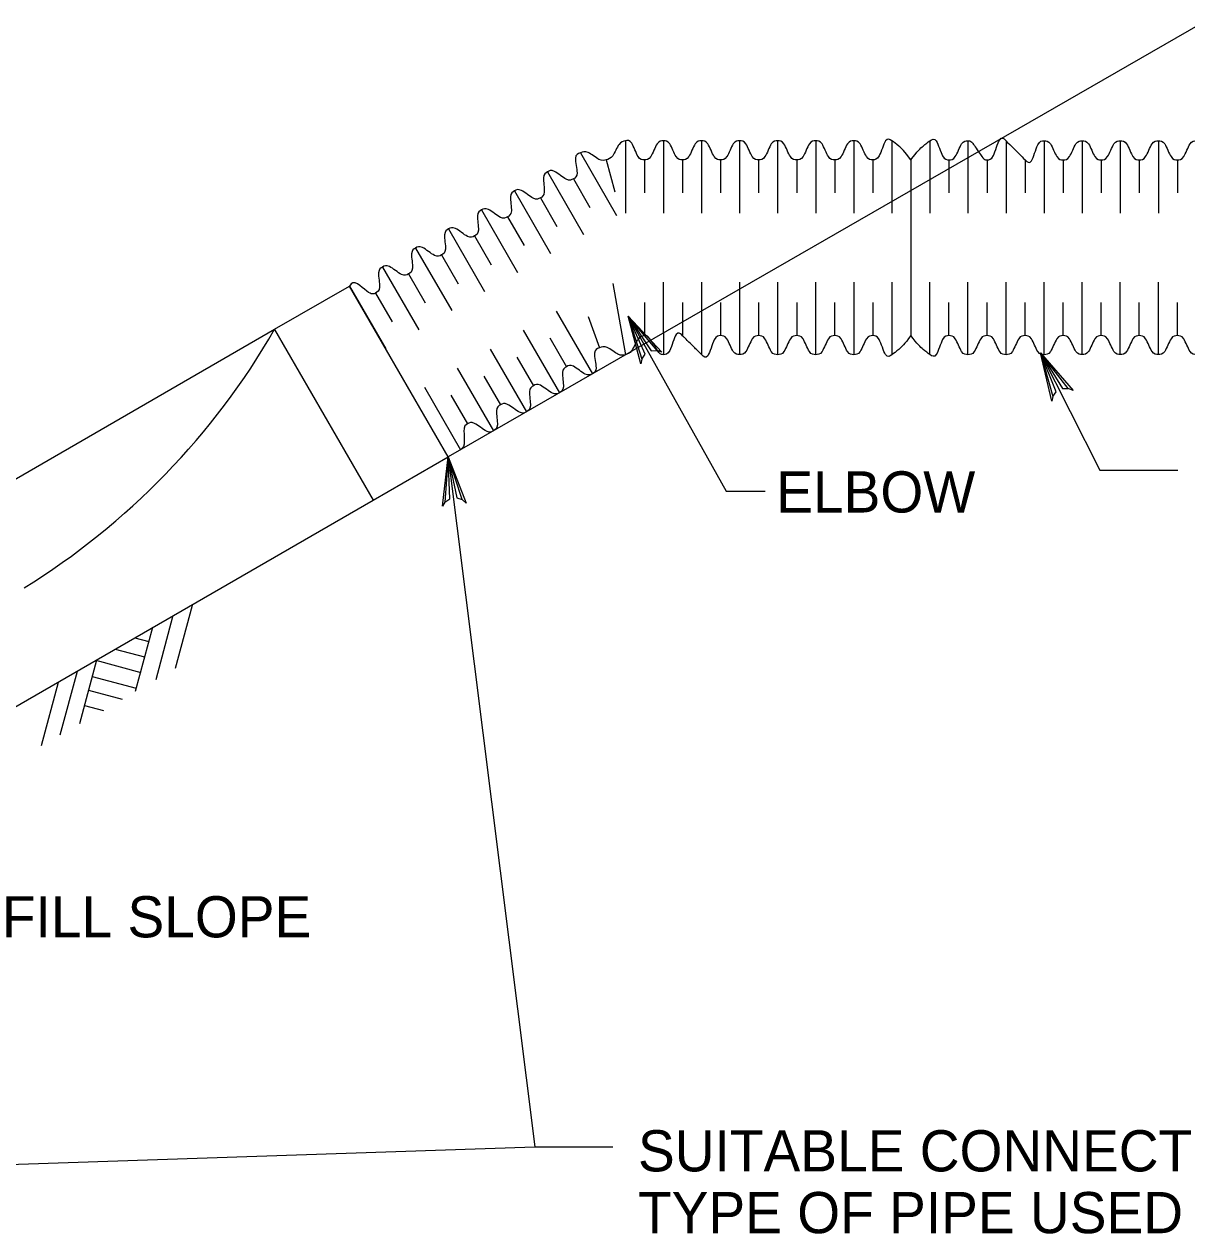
# Model space of a CAD drawing. Extents: x 636462 to 637367, y 299944 to 300538.
# Drawn here: x 636692.5 to 636777.1, y 300064.4 to 300152.4 of the extents above; entities that cross this region are included whole.
import ezdxf

# ---------------------------------------------------------------- set-up
doc = ezdxf.new("R2010")
doc.units = 0
doc.layers.add('Default', color=7, linetype='Continuous')

# ---------------------------------------------------------------- blocks, each defined once
blk = doc.blocks.new('SC9446')
at = {"layer": 'Default'}
blk.add_line((0, 0), (0, 0), dxfattribs=at)

msp = doc.modelspace()

# ---------------------------------------------------------------- linework, layer by layer
at = {"layer": 'Default'}
for p, q in [((636778.087, 300152.423), (636723.371, 300120.938)), ((636736.259, 300143.941), (636736.259, 300138.678)), ((636739.029, 300143.941), (636739.029, 300138.678)), ((636741.799, 300143.941), (636741.799, 300138.678)), ((636744.569, 300143.941), (636744.569, 300138.678)), ((636747.339, 300143.941), (636747.339, 300138.678)), ((636750.109, 300143.941), (636750.109, 300138.678)), ((636752.879, 300143.941), (636752.879, 300138.678)), ((636755.649, 300143.941), (636755.649, 300139.511)), ((636758.417, 300143.941), (636758.417, 300141.104)), ((636761.187, 300143.941), (636761.187, 300142.698)), ((636763.957, 300143.941), (636763.957, 300143.727)), ((636766.726, 300143.941), (636766.726, 300138.678)), ((636769.496, 300143.941), (636769.496, 300138.678)), ((636772.266, 300143.941), (636772.266, 300138.678)), ((636775.036, 300143.941), (636775.036, 300138.678)), ((636732.984, 300143.064), (636735.615, 300138.504)), ((636763.957, 300143.727), (636763.957, 300138.678)), ((636734.875, 300142.556), (636735.5, 300140.225)), ((636737.644, 300142.556), (636737.644, 300140.143)), ((636740.414, 300142.556), (636740.414, 300140.141)), ((636743.184, 300142.556), (636743.184, 300140.143)), ((636745.954, 300142.556), (636745.954, 300140.143)), ((636748.724, 300142.556), (636748.724, 300140.141)), ((636751.494, 300142.556), (636751.494, 300140.143)), ((636754.262, 300142.556), (636754.262, 300140.143)), ((636757.032, 300142.556), (636757.032, 300140.307)), ((636759.802, 300142.556), (636759.802, 300141.901)), ((636761.187, 300142.698), (636761.187, 300141.723)), ((636762.572, 300142.556), (636762.572, 300140.143)), ((636762.572, 300142.556), (636762.572, 300140.143)), ((636765.341, 300142.556), (636765.341, 300140.141)), ((636768.111, 300142.556), (636768.111, 300140.141)), ((636770.881, 300142.556), (636770.881, 300140.143)), ((636773.651, 300142.556), (636773.651, 300140.141)), ((636776.421, 300142.556), (636776.421, 300140.141)), ((636730.585, 300141.679), (636733.217, 300137.121)), ((636759.802, 300141.901), (636759.802, 300140.888)), ((636761.187, 300141.723), (636761.187, 300138.678)), ((636732.476, 300141.171), (636733.685, 300139.081)), ((636758.417, 300141.104), (636758.417, 300140.054)), ((636759.802, 300140.888), (636759.802, 300140.143)), ((636728.187, 300140.294), (636730.818, 300135.736)), ((636730.078, 300139.786), (636731.286, 300137.696)), ((636757.032, 300140.307), (636757.032, 300129.762)), ((636758.417, 300140.054), (636758.417, 300138.678)), ((636725.788, 300138.909), (636728.42, 300134.349)), ((636755.649, 300139.511), (636755.649, 300138.678)), ((636757.032, 300139.219), (636757.032, 300129.762)), ((636727.679, 300138.401), (636728.888, 300136.311)), ((636723.39, 300137.524), (636726.021, 300132.966)), ((636725.281, 300137.016), (636726.487, 300134.926)), ((636720.991, 300136.139), (636723.623, 300131.581)), ((636722.882, 300135.631), (636724.089, 300133.541)), ((636718.591, 300134.754), (636721.224, 300130.196)), ((636720.484, 300134.248), (636721.69, 300132.156)), ((636735.347, 300133.562), (636736.259, 300128.377)), ((636739.029, 300129.948), (636739.029, 300133.642)), ((636741.799, 300133.642), (636741.799, 300131.542)), ((636744.569, 300133.642), (636744.569, 300131.713)), ((636747.339, 300133.642), (636747.339, 300133.382)), ((636747.339, 300133.382), (636747.339, 300128.377)), ((636750.109, 300128.377), (636750.109, 300133.642)), ((636752.879, 300133.642), (636752.877, 300128.377)), ((636755.649, 300133.642), (636755.649, 300128.377)), ((636758.417, 300128.379), (636758.417, 300133.642)), ((636761.187, 300128.377), (636761.187, 300133.642)), ((636763.957, 300128.377), (636763.957, 300133.642)), ((636766.726, 300128.377), (636766.726, 300133.642)), ((636769.496, 300128.379), (636769.496, 300133.642)), ((636772.266, 300128.379), (636772.266, 300133.642)), ((636775.036, 300128.379), (636775.036, 300133.642)), ((636710.741, 300130.223), (636716.192, 300133.371)), ((636716.192, 300133.369), (636718.826, 300128.811)), ((636723.371, 300120.938), (636716.192, 300133.369)), ((636718.085, 300132.863), (636719.292, 300130.771)), ((636737.644, 300132.177), (636737.644, 300129.762)), ((636740.414, 300132.177), (636740.414, 300130.745)), ((636743.184, 300132.177), (636743.184, 300130.88)), ((636744.569, 300131.713), (636744.569, 300128.379)), ((636745.954, 300132.177), (636745.954, 300129.762)), ((636748.724, 300132.177), (636748.724, 300129.762)), ((636751.494, 300129.762), (636751.494, 300132.177)), ((636754.262, 300132.177), (636754.262, 300129.762)), ((636759.802, 300129.762), (636759.802, 300132.177)), ((636762.572, 300129.762), (636762.572, 300132.177)), ((636765.341, 300129.764), (636765.341, 300132.177)), ((636768.111, 300129.764), (636768.111, 300132.177)), ((636770.881, 300129.762), (636770.881, 300132.177)), ((636773.651, 300129.764), (636773.651, 300132.177)), ((636776.421, 300129.764), (636776.421, 300132.177)), ((636731.23, 300131.552), (636733.861, 300126.994)), ((636733.542, 300131.153), (636734.369, 300128.885)), ((636740.414, 300130.745), (636740.414, 300129.762)), ((636741.799, 300131.542), (636741.799, 300130.045)), ((636743.184, 300130.88), (636743.184, 300129.762)), ((636628.963, 300083.009), (636710.741, 300130.223)), ((636710.741, 300130.221), (636717.919, 300117.79)), ((636728.831, 300130.167), (636731.463, 300125.609)), ((636739.029, 300129.948), (636739.029, 300128.377)), ((636741.799, 300130.045), (636741.799, 300128.377)), ((636730.762, 300129.592), (636731.97, 300127.5)), ((636726.433, 300128.782), (636729.064, 300124.224)), ((636728.363, 300128.207), (636729.572, 300126.117)), ((636724.034, 300127.397), (636726.666, 300122.839)), ((636725.965, 300126.822), (636727.171, 300124.73)), ((636721.636, 300126.012), (636724.267, 300121.454)), ((636723.566, 300125.437), (636724.773, 300123.347)), ((636717.917, 300117.79), (636723.371, 300120.938)), ((636636.14, 300070.576), (636717.917, 300117.79)), ((636703.533, 300105.571), (636704.762, 300110.152)), ((636702.12, 300104.755), (636703.348, 300109.336)), ((636700.628, 300103.892), (636701.877, 300108.549)), ((636700.582, 300107.781), (636701.598, 300107.51)), ((636696.562, 300101.546), (636697.804, 300106.178)), ((636697.741, 300106.14), (636701.01, 300105.265)), ((636699.153, 300106.956), (636701.283, 300106.385)), ((636695.149, 300100.73), (636696.39, 300105.361)), ((636693.783, 300099.941), (636695.017, 300104.547)), ((636697.479, 300104.963), (636700.672, 300104.107)), ((636697.212, 300103.972), (636699.64, 300103.322)), ((636696.914, 300102.858), (636698.301, 300102.487))]:
    msp.add_line(p, q, dxfattribs=at)
for points in [[(636736.455, 300131.191), (636743.594, 300118.456), (636746.429, 300118.456)], [(636737.461, 300128.054), (636737.396, 300127.711), (636736.455, 300131.191), (636737.461, 300128.054), (636737.693, 300128.407), (636736.455, 300131.191), (636738.148, 300128.666), (636738.565, 300128.688), (636736.455, 300131.191), (636738.923, 300128.563), (636738.565, 300128.688)], [(636766.471, 300128.501), (636770.784, 300119.967), (636776.454, 300119.967)], [(636767.355, 300125.327), (636767.276, 300124.986), (636766.471, 300128.501), (636767.355, 300125.327), (636767.6, 300125.67), (636766.471, 300128.501), (636768.065, 300125.911), (636768.482, 300125.917), (636766.471, 300128.501), (636768.835, 300125.779), (636768.482, 300125.917)], [(636723.136, 300117.652), (636722.947, 300117.358), (636723.371, 300120.938), (636723.136, 300117.652), (636723.482, 300117.893), (636723.371, 300120.938), (636724.001, 300117.963), (636724.396, 300117.829), (636723.371, 300120.938), (636724.682, 300117.579), (636724.396, 300117.829)], [(636723.371, 300120.938), (636729.675, 300070.742), (636735.344, 300070.742)], [(636630.688, 300067.428), (636729.675, 300070.742), (636735.344, 300070.742)]]:
    msp.add_lwpolyline(points, dxfattribs=at)
msp.add_arc((636664.466, 300156.825), 53.378, 301.71048, 330.10623, dxfattribs=at)
for points in [[(636757.032, 300142.556), (636756.573, 300143.171), (636756.111, 300143.614), (636755.649, 300143.941), (636755.187, 300144.269), (636754.724, 300142.556), (636754.262, 300142.556), (636753.801, 300142.556), (636753.34, 300143.941), (636752.879, 300143.941), (636752.417, 300143.941), (636751.956, 300142.556), (636751.494, 300142.556), (636751.032, 300142.556), (636750.571, 300143.941), (636750.109, 300143.941), (636749.647, 300143.941), (636749.186, 300142.556), (636748.724, 300142.556), (636748.262, 300142.556), (636747.801, 300143.941), (636747.339, 300143.941), (636746.878, 300143.941), (636746.416, 300142.556), (636745.954, 300142.556), (636745.493, 300142.556), (636745.031, 300143.941), (636744.569, 300143.941), (636744.108, 300143.941), (636743.646, 300142.556), (636743.184, 300142.556), (636742.723, 300142.556), (636742.261, 300143.941), (636741.799, 300143.941), (636741.338, 300143.941), (636740.876, 300142.556), (636740.414, 300142.556), (636739.953, 300142.556), (636739.491, 300143.941), (636739.029, 300143.941), (636738.568, 300143.941), (636738.106, 300142.556), (636737.644, 300142.556), (636737.183, 300142.556), (636736.721, 300144.028), (636736.259, 300143.941), (636735.798, 300143.854), (636735.336, 300142.679), (636734.875, 300142.556), (636734.413, 300142.432), (636733.491, 300143.247), (636732.984, 300143.064), (636732.477, 300142.88), (636732.876, 300141.402), (636732.476, 300141.171), (636732.076, 300140.94), (636730.985, 300141.909), (636730.585, 300141.679), (636730.185, 300141.448), (636730.478, 300140.017), (636730.078, 300139.786), (636729.678, 300139.555), (636728.587, 300140.524), (636728.187, 300140.294), (636727.787, 300140.063), (636728.079, 300138.632), (636727.679, 300138.401), (636727.279, 300138.17), (636726.188, 300139.139), (636725.788, 300138.909), (636725.388, 300138.678), (636725.681, 300137.247), (636725.281, 300137.016), (636724.881, 300136.786), (636723.79, 300137.754), (636723.39, 300137.524), (636722.99, 300137.293), (636723.282, 300135.862), (636722.882, 300135.631), (636722.482, 300135.401), (636721.391, 300136.37), (636720.991, 300136.139), (636720.592, 300135.908), (636720.883, 300134.479), (636720.484, 300134.248), (636720.084, 300134.017), (636718.991, 300134.985), (636718.591, 300134.754), (636718.191, 300134.523), (636718.485, 300133.094), (636718.085, 300132.863), (636717.685, 300132.632), (636716.433, 300133.983), (636716.192, 300133.369)], [(636757.032, 300142.556), (636757.493, 300143.172), (636757.955, 300143.614), (636758.417, 300143.941), (636758.878, 300144.268), (636759.34, 300142.556), (636759.802, 300142.556), (636760.263, 300142.556), (636760.725, 300143.941), (636761.187, 300143.941), (636761.442, 300143.941), (636761.697, 300143.517), (636761.953, 300143.138)], [(636761.953, 300143.138), (636762.159, 300142.832), (636762.365, 300142.556), (636762.572, 300142.556), (636763.033, 300142.556), (636763.495, 300144.402), (636763.957, 300143.941), (636763.995, 300143.902), (636764.034, 300143.864), (636764.072, 300143.825)], [(636764.072, 300143.825), (636764.495, 300143.402), (636764.918, 300142.979), (636765.341, 300142.556), (636765.803, 300142.094), (636766.265, 300143.941), (636766.726, 300143.941), (636767.188, 300143.941), (636767.65, 300142.556), (636768.111, 300142.556), (636768.573, 300142.556), (636769.035, 300143.941), (636769.496, 300143.941), (636769.958, 300143.941), (636770.42, 300142.556), (636770.881, 300142.556), (636771.343, 300142.556), (636771.805, 300143.941), (636772.266, 300143.941), (636772.728, 300143.941), (636773.19, 300142.556), (636773.651, 300142.556), (636774.113, 300142.556), (636774.575, 300143.941), (636775.036, 300143.941), (636775.498, 300143.941), (636775.959, 300142.556), (636776.421, 300142.556), (636776.882, 300142.556), (636777.343, 300143.941), (636777.804, 300143.941), (636778.266, 300143.941), (636778.727, 300142.422), (636779.189, 300142.556), (636779.252, 300142.574), (636779.315, 300142.727), (636779.378, 300142.745)], [(636740.759, 300129.42), (636740.644, 300129.534), (636740.529, 300129.648), (636740.414, 300129.762), (636739.953, 300130.22), (636739.491, 300128.377), (636739.029, 300128.377), (636738.726, 300128.377), (636738.422, 300129.013), (636738.119, 300129.424)], [(636738.119, 300129.424), (636737.961, 300129.638), (636737.803, 300129.792), (636737.644, 300129.762), (636737.183, 300129.675), (636736.721, 300128.5), (636736.259, 300128.377), (636735.798, 300128.253), (636734.876, 300129.068), (636734.369, 300128.885), (636733.862, 300128.701), (636734.261, 300127.225), (636733.861, 300126.994), (636733.461, 300126.763), (636732.37, 300127.73), (636731.97, 300127.5), (636731.571, 300127.269), (636731.862, 300125.84), (636731.463, 300125.609), (636731.063, 300125.378), (636729.972, 300126.348), (636729.572, 300126.117), (636729.172, 300125.886), (636729.464, 300124.455), (636729.064, 300124.224), (636728.664, 300123.993), (636727.571, 300124.961), (636727.171, 300124.73), (636726.772, 300124.499), (636727.065, 300123.07), (636726.666, 300122.839), (636726.266, 300122.608), (636725.173, 300123.578), (636724.773, 300123.347), (636724.373, 300123.116), (636724.667, 300121.685), (636724.267, 300121.454)], [(636757.032, 300129.762), (636756.573, 300129.146), (636756.111, 300128.704), (636755.649, 300128.377), (636755.187, 300128.049), (636754.724, 300129.762), (636754.262, 300129.762), (636753.8, 300129.762), (636753.338, 300128.377), (636752.877, 300128.377), (636752.416, 300128.377), (636751.955, 300129.762), (636751.494, 300129.762), (636751.032, 300129.762), (636750.571, 300128.377), (636750.109, 300128.377), (636749.647, 300128.377), (636749.186, 300129.762), (636748.724, 300129.762), (636748.262, 300129.762), (636747.801, 300128.377), (636747.339, 300128.377), (636746.878, 300128.377), (636746.416, 300129.762), (636745.954, 300129.762), (636745.493, 300129.762), (636745.031, 300128.379), (636744.569, 300128.379), (636744.108, 300128.379), (636743.646, 300129.762), (636743.184, 300129.762), (636742.722, 300129.762), (636742.261, 300127.917), (636741.799, 300128.377), (636741.452, 300128.723), (636741.106, 300129.073), (636740.759, 300129.42)], [(636779.378, 300129.575), (636779.315, 300129.593), (636779.252, 300129.746), (636779.189, 300129.764), (636778.727, 300129.897), (636778.266, 300128.379), (636777.804, 300128.379), (636777.343, 300128.379), (636776.882, 300129.764), (636776.421, 300129.764), (636775.959, 300129.764), (636775.498, 300128.379), (636775.036, 300128.379), (636774.575, 300128.379), (636774.113, 300129.764), (636773.651, 300129.764), (636773.19, 300129.764), (636772.728, 300128.379), (636772.266, 300128.379), (636771.805, 300128.379), (636771.343, 300129.762), (636770.881, 300129.762), (636770.42, 300129.762), (636769.958, 300128.379), (636769.496, 300128.379), (636769.034, 300128.379), (636768.573, 300129.764), (636768.111, 300129.764), (636767.65, 300129.764), (636767.188, 300128.377), (636766.726, 300128.377), (636766.265, 300128.377), (636765.803, 300129.764), (636765.341, 300129.764), (636764.88, 300129.764), (636764.418, 300128.377), (636763.957, 300128.377), (636763.495, 300128.377), (636763.033, 300129.762), (636762.572, 300129.762), (636762.11, 300129.762), (636761.648, 300128.377), (636761.187, 300128.377), (636760.725, 300128.377), (636760.263, 300129.762), (636759.802, 300129.762), (636759.34, 300129.762), (636758.878, 300128.053), (636758.417, 300128.379), (636757.955, 300128.705), (636757.493, 300129.146), (636757.032, 300129.762)]]:
    msp.add_open_spline(points, degree=3, dxfattribs=at)

# ---------------------------------------------------------------- block references
at = {"layer": 'Default', "xscale": 2.753831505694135, "yscale": 2.753831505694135}
for p in [(636750.109, 300138.678), (636750.109, 300136.16)]:
    msp.add_blockref('SC9446', p, dxfattribs=at)

# ---------------------------------------------------------------- texts
at = {"layer": 'Default'}
for s, height, p in [('ELBOW', 2.998, (636747.236, 300116.893)), ('FILL SLOPE', 2.998, (636690.902, 300085.982)), ('SUITABLE CONNECTION FOR THE', 2.99804, (636737.179, 300068.955)), ('TYPE OF PIPE USED ON FILL SLOPE', 2.99804, (636737.179, 300064.458))]:
    msp.add_text(s, height=height, dxfattribs=at).set_placement(p)

doc.saveas('drawing.dxf')
